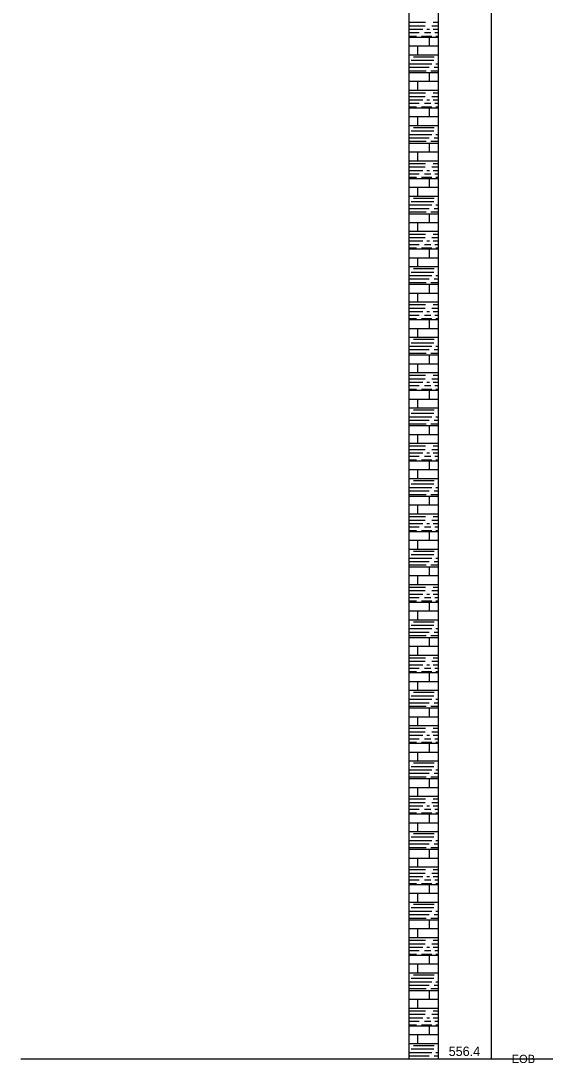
# Model space of a CAD drawing. Extents: x -0.01 to 0.83, y -0.77 to 1.27.
# Drawn here: x 0 to 0.372, y -0.768 to -0.03 of the extents above; entities that cross this region are included whole.
import ezdxf

# ---------------------------------------------------------------- set-up
doc = ezdxf.new("R2010")
doc.units = 0

msp = doc.modelspace()

# ---------------------------------------------------------------- linework, layer by layer
for points in [[(0.29583, 1.22083), (0.29583, -0.76533)], [(0.29583, 1.22083), (0.29583, -0.76533)], [(0.33333, 1.22083), (0.33333, -0.76533)], [(0.33333, 1.22083), (0.33333, -0.76533)], [(0.275, 1.19583), (0.275, -0.76533)], [(0.275, 0.09567), (0.275, -0.76533)], [(0.275, -0.03125), (0.28683, -0.03125)], [(0.275, -0.03375), (0.28642, -0.03375)], [(0.275, -0.03617), (0.28483, -0.03617)], [(0.28767, -0.03617), (0.28967, -0.03617)], [(0.29133, -0.03375), (0.29583, -0.03375)], [(0.29217, -0.03125), (0.29583, -0.03125)], [(0.29217, -0.03617), (0.29583, -0.03617)], [(0.275, -0.03858), (0.28233, -0.03858)], [(0.275, -0.04108), (0.28033, -0.04108)], [(0.275, -0.04183), (0.29583, -0.04183)], [(0.284, -0.04108), (0.29133, -0.04108)], [(0.286, -0.03858), (0.2905, -0.03858)], [(0.28958, -0.04808), (0.28958, -0.04183)], [(0.29342, -0.03858), (0.29583, -0.03858)], [(0.29417, -0.04108), (0.29583, -0.04108)], [(0.275, -0.04808), (0.29583, -0.04808)], [(0.28125, -0.05433), (0.28125, -0.04808)], [(0.275, -0.05433), (0.29583, -0.05433)], [(0.27667, -0.05817), (0.29258, -0.05817)], [(0.27825, -0.05575), (0.293, -0.05575)], [(0.29542, -0.05575), (0.29583, -0.05575)], [(0.275, -0.06067), (0.29133, -0.06067)], [(0.275, -0.06308), (0.28933, -0.06308)], [(0.275, -0.06558), (0.28725, -0.06558)], [(0.2905, -0.06558), (0.29583, -0.06558)], [(0.293, -0.06308), (0.29583, -0.06308)], [(0.29417, -0.06067), (0.29583, -0.06067)], [(0.275, -0.06683), (0.29583, -0.06683)], [(0.275, -0.07308), (0.29583, -0.07308)], [(0.28125, -0.07933), (0.28125, -0.07308)], [(0.28958, -0.07308), (0.28958, -0.06683)], [(0.275, -0.07933), (0.29583, -0.07933)], [(0.275, -0.08125), (0.28683, -0.08125)], [(0.275, -0.08375), (0.28642, -0.08375)], [(0.275, -0.08617), (0.28483, -0.08617)], [(0.28767, -0.08617), (0.28967, -0.08617)], [(0.29133, -0.08375), (0.29583, -0.08375)], [(0.29217, -0.08125), (0.29583, -0.08125)], [(0.29217, -0.08617), (0.29583, -0.08617)], [(0.275, -0.08858), (0.28233, -0.08858)], [(0.275, -0.09108), (0.28033, -0.09108)], [(0.275, -0.09183), (0.29583, -0.09183)], [(0.284, -0.09108), (0.29133, -0.09108)], [(0.286, -0.08858), (0.2905, -0.08858)], [(0.28958, -0.09808), (0.28958, -0.09183)], [(0.29342, -0.08858), (0.29583, -0.08858)], [(0.29417, -0.09108), (0.29583, -0.09108)], [(0.275, -0.09808), (0.29583, -0.09808)], [(0.28125, -0.10433), (0.28125, -0.09808)], [(0.275, -0.10433), (0.29583, -0.10433)], [(0.275, -0.11067), (0.29133, -0.11067)], [(0.27667, -0.10817), (0.29258, -0.10817)], [(0.27825, -0.10575), (0.293, -0.10575)], [(0.29417, -0.11067), (0.29583, -0.11067)], [(0.29542, -0.10575), (0.29583, -0.10575)], [(0.275, -0.11308), (0.28933, -0.11308)], [(0.275, -0.11558), (0.28725, -0.11558)], [(0.275, -0.11683), (0.29583, -0.11683)], [(0.28958, -0.12308), (0.28958, -0.11683)], [(0.2905, -0.11558), (0.29583, -0.11558)], [(0.293, -0.11308), (0.29583, -0.11308)], [(0.275, -0.12308), (0.29583, -0.12308)], [(0.28125, -0.12933), (0.28125, -0.12308)], [(0.275, -0.12933), (0.29583, -0.12933)], [(0.275, -0.13125), (0.28683, -0.13125)], [(0.29217, -0.13125), (0.29583, -0.13125)], [(0.275, -0.13375), (0.28642, -0.13375)], [(0.275, -0.13617), (0.28483, -0.13617)], [(0.275, -0.13858), (0.28233, -0.13858)], [(0.286, -0.13858), (0.2905, -0.13858)], [(0.28767, -0.13617), (0.28967, -0.13617)], [(0.29133, -0.13375), (0.29583, -0.13375)], [(0.29217, -0.13617), (0.29583, -0.13617)], [(0.29342, -0.13858), (0.29583, -0.13858)], [(0.275, -0.14108), (0.28033, -0.14108)], [(0.275, -0.14183), (0.29583, -0.14183)], [(0.284, -0.14108), (0.29133, -0.14108)], [(0.28958, -0.14808), (0.28958, -0.14183)], [(0.29417, -0.14108), (0.29583, -0.14108)], [(0.275, -0.14808), (0.29583, -0.14808)], [(0.275, -0.15433), (0.29583, -0.15433)], [(0.28125, -0.15433), (0.28125, -0.14808)], [(0.275, -0.16067), (0.29133, -0.16067)], [(0.27667, -0.15817), (0.29258, -0.15817)], [(0.27825, -0.15575), (0.293, -0.15575)], [(0.29417, -0.16067), (0.29583, -0.16067)], [(0.29542, -0.15575), (0.29583, -0.15575)], [(0.275, -0.16308), (0.28933, -0.16308)], [(0.275, -0.16558), (0.28725, -0.16558)], [(0.275, -0.16683), (0.29583, -0.16683)], [(0.28958, -0.17308), (0.28958, -0.16683)], [(0.2905, -0.16558), (0.29583, -0.16558)], [(0.293, -0.16308), (0.29583, -0.16308)], [(0.275, -0.17308), (0.29583, -0.17308)], [(0.28125, -0.17933), (0.28125, -0.17308)], [(0.275, -0.17933), (0.29583, -0.17933)], [(0.275, -0.18125), (0.28683, -0.18125)], [(0.275, -0.18375), (0.28642, -0.18375)], [(0.29133, -0.18375), (0.29583, -0.18375)], [(0.29217, -0.18125), (0.29583, -0.18125)], [(0.275, -0.18617), (0.28483, -0.18617)], [(0.275, -0.18858), (0.28233, -0.18858)], [(0.275, -0.19108), (0.28033, -0.19108)], [(0.275, -0.19183), (0.29583, -0.19183)], [(0.284, -0.19108), (0.29133, -0.19108)], [(0.286, -0.18858), (0.2905, -0.18858)], [(0.28767, -0.18617), (0.28967, -0.18617)], [(0.28958, -0.19808), (0.28958, -0.19183)], [(0.29217, -0.18617), (0.29583, -0.18617)], [(0.29342, -0.18858), (0.29583, -0.18858)], [(0.29417, -0.19108), (0.29583, -0.19108)], [(0.275, -0.19808), (0.29583, -0.19808)], [(0.28125, -0.20433), (0.28125, -0.19808)], [(0.275, -0.20433), (0.29583, -0.20433)], [(0.27825, -0.20575), (0.293, -0.20575)], [(0.29542, -0.20575), (0.29583, -0.20575)], [(0.275, -0.21067), (0.29133, -0.21067)], [(0.275, -0.21308), (0.28933, -0.21308)], [(0.27667, -0.20817), (0.29258, -0.20817)], [(0.293, -0.21308), (0.29583, -0.21308)], [(0.29417, -0.21067), (0.29583, -0.21067)], [(0.275, -0.21558), (0.28725, -0.21558)], [(0.275, -0.21683), (0.29583, -0.21683)], [(0.28958, -0.22308), (0.28958, -0.21683)], [(0.2905, -0.21558), (0.29583, -0.21558)], [(0.275, -0.22308), (0.29583, -0.22308)], [(0.28125, -0.22933), (0.28125, -0.22308)], [(0.275, -0.22933), (0.29583, -0.22933)], [(0.275, -0.23125), (0.28683, -0.23125)], [(0.275, -0.23375), (0.28642, -0.23375)], [(0.275, -0.23617), (0.28483, -0.23617)], [(0.28767, -0.23617), (0.28967, -0.23617)], [(0.29133, -0.23375), (0.29583, -0.23375)], [(0.29217, -0.23125), (0.29583, -0.23125)], [(0.29217, -0.23617), (0.29583, -0.23617)], [(0.275, -0.23858), (0.28233, -0.23858)], [(0.275, -0.24108), (0.28033, -0.24108)], [(0.275, -0.24183), (0.29583, -0.24183)], [(0.284, -0.24108), (0.29133, -0.24108)], [(0.286, -0.23858), (0.2905, -0.23858)], [(0.28958, -0.24808), (0.28958, -0.24183)], [(0.29342, -0.23858), (0.29583, -0.23858)], [(0.29417, -0.24108), (0.29583, -0.24108)], [(0.275, -0.24808), (0.29583, -0.24808)], [(0.28125, -0.25433), (0.28125, -0.24808)], [(0.275, -0.25433), (0.29583, -0.25433)], [(0.27667, -0.25817), (0.29258, -0.25817)], [(0.27825, -0.25575), (0.293, -0.25575)], [(0.29542, -0.25575), (0.29583, -0.25575)], [(0.275, -0.26067), (0.29133, -0.26067)], [(0.275, -0.26308), (0.28933, -0.26308)], [(0.275, -0.26558), (0.28725, -0.26558)], [(0.2905, -0.26558), (0.29583, -0.26558)], [(0.293, -0.26308), (0.29583, -0.26308)], [(0.29417, -0.26067), (0.29583, -0.26067)], [(0.275, -0.26683), (0.29583, -0.26683)], [(0.28958, -0.27308), (0.28958, -0.26683)], [(0.275, -0.27308), (0.29583, -0.27308)], [(0.275, -0.27933), (0.29583, -0.27933)], [(0.28125, -0.27933), (0.28125, -0.27308)], [(0.275, -0.28125), (0.28683, -0.28125)], [(0.275, -0.28375), (0.28642, -0.28375)], [(0.275, -0.28617), (0.28483, -0.28617)], [(0.28767, -0.28617), (0.28967, -0.28617)], [(0.29133, -0.28375), (0.29583, -0.28375)], [(0.29217, -0.28125), (0.29583, -0.28125)], [(0.29217, -0.28617), (0.29583, -0.28617)], [(0.275, -0.28858), (0.28233, -0.28858)], [(0.275, -0.29108), (0.28033, -0.29108)], [(0.275, -0.29183), (0.29583, -0.29183)], [(0.284, -0.29108), (0.29133, -0.29108)], [(0.286, -0.28858), (0.2905, -0.28858)], [(0.28958, -0.29808), (0.28958, -0.29183)], [(0.29342, -0.28858), (0.29583, -0.28858)], [(0.29417, -0.29108), (0.29583, -0.29108)], [(0.275, -0.29808), (0.29583, -0.29808)], [(0.28125, -0.30433), (0.28125, -0.29808)], [(0.275, -0.30433), (0.29583, -0.30433)], [(0.27667, -0.30817), (0.29258, -0.30817)], [(0.27825, -0.30575), (0.293, -0.30575)], [(0.29542, -0.30575), (0.29583, -0.30575)], [(0.275, -0.31067), (0.29133, -0.31067)], [(0.275, -0.31308), (0.28933, -0.31308)], [(0.275, -0.31558), (0.28725, -0.31558)], [(0.275, -0.31683), (0.29583, -0.31683)], [(0.28958, -0.32308), (0.28958, -0.31683)], [(0.2905, -0.31558), (0.29583, -0.31558)], [(0.293, -0.31308), (0.29583, -0.31308)], [(0.29417, -0.31067), (0.29583, -0.31067)], [(0.275, -0.32308), (0.29583, -0.32308)], [(0.28125, -0.32933), (0.28125, -0.32308)], [(0.275, -0.32933), (0.29583, -0.32933)], [(0.275, -0.33125), (0.28683, -0.33125)], [(0.29217, -0.33125), (0.29583, -0.33125)], [(0.275, -0.33375), (0.28642, -0.33375)], [(0.275, -0.33617), (0.28483, -0.33617)], [(0.275, -0.33858), (0.28233, -0.33858)], [(0.286, -0.33858), (0.2905, -0.33858)], [(0.28767, -0.33617), (0.28967, -0.33617)], [(0.29133, -0.33375), (0.29583, -0.33375)], [(0.29217, -0.33617), (0.29583, -0.33617)], [(0.29342, -0.33858), (0.29583, -0.33858)], [(0.275, -0.34108), (0.28033, -0.34108)], [(0.275, -0.34183), (0.29583, -0.34183)], [(0.284, -0.34108), (0.29133, -0.34108)], [(0.28958, -0.34808), (0.28958, -0.34183)], [(0.29417, -0.34108), (0.29583, -0.34108)], [(0.275, -0.34808), (0.29583, -0.34808)], [(0.28125, -0.35433), (0.28125, -0.34808)], [(0.275, -0.35433), (0.29583, -0.35433)], [(0.275, -0.36067), (0.29133, -0.36067)], [(0.27667, -0.35817), (0.29258, -0.35817)], [(0.27825, -0.35575), (0.293, -0.35575)], [(0.29417, -0.36067), (0.29583, -0.36067)], [(0.29542, -0.35575), (0.29583, -0.35575)], [(0.275, -0.36308), (0.28933, -0.36308)], [(0.275, -0.36558), (0.28725, -0.36558)], [(0.275, -0.36683), (0.29583, -0.36683)], [(0.28958, -0.37308), (0.28958, -0.36683)], [(0.2905, -0.36558), (0.29583, -0.36558)], [(0.293, -0.36308), (0.29583, -0.36308)], [(0.275, -0.37308), (0.29583, -0.37308)], [(0.28125, -0.37933), (0.28125, -0.37308)], [(0.275, -0.37933), (0.29583, -0.37933)], [(0.275, -0.38125), (0.28683, -0.38125)], [(0.275, -0.38375), (0.28642, -0.38375)], [(0.29133, -0.38375), (0.29583, -0.38375)], [(0.29217, -0.38125), (0.29583, -0.38125)], [(0.275, -0.38617), (0.28483, -0.38617)], [(0.275, -0.38858), (0.28233, -0.38858)], [(0.275, -0.39108), (0.28033, -0.39108)], [(0.284, -0.39108), (0.29133, -0.39108)], [(0.286, -0.38858), (0.2905, -0.38858)], [(0.28767, -0.38617), (0.28967, -0.38617)], [(0.29217, -0.38617), (0.29583, -0.38617)], [(0.29342, -0.38858), (0.29583, -0.38858)], [(0.29417, -0.39108), (0.29583, -0.39108)], [(0.275, -0.39183), (0.29583, -0.39183)], [(0.275, -0.39808), (0.29583, -0.39808)], [(0.28125, -0.40433), (0.28125, -0.39808)], [(0.28958, -0.39808), (0.28958, -0.39183)], [(0.275, -0.40433), (0.29583, -0.40433)], [(0.27825, -0.40575), (0.293, -0.40575)], [(0.29542, -0.40575), (0.29583, -0.40575)], [(0.275, -0.41067), (0.29133, -0.41067)], [(0.275, -0.41308), (0.28933, -0.41308)], [(0.27667, -0.40817), (0.29258, -0.40817)], [(0.293, -0.41308), (0.29583, -0.41308)], [(0.29417, -0.41067), (0.29583, -0.41067)], [(0.275, -0.41558), (0.28725, -0.41558)], [(0.275, -0.41683), (0.29583, -0.41683)], [(0.28958, -0.42308), (0.28958, -0.41683)], [(0.2905, -0.41558), (0.29583, -0.41558)], [(0.275, -0.42308), (0.29583, -0.42308)], [(0.28125, -0.42933), (0.28125, -0.42308)], [(0.275, -0.42933), (0.29583, -0.42933)], [(0.275, -0.43125), (0.28683, -0.43125)], [(0.275, -0.43375), (0.28642, -0.43375)], [(0.29133, -0.43375), (0.29583, -0.43375)], [(0.29217, -0.43125), (0.29583, -0.43125)], [(0.275, -0.43617), (0.28483, -0.43617)], [(0.275, -0.43858), (0.28233, -0.43858)], [(0.275, -0.44108), (0.28033, -0.44108)], [(0.275, -0.44183), (0.29583, -0.44183)], [(0.284, -0.44108), (0.29133, -0.44108)], [(0.286, -0.43858), (0.2905, -0.43858)], [(0.28767, -0.43617), (0.28967, -0.43617)], [(0.28958, -0.44808), (0.28958, -0.44183)], [(0.29217, -0.43617), (0.29583, -0.43617)], [(0.29342, -0.43858), (0.29583, -0.43858)], [(0.29417, -0.44108), (0.29583, -0.44108)], [(0.275, -0.44808), (0.29583, -0.44808)], [(0.28125, -0.45433), (0.28125, -0.44808)], [(0.275, -0.45433), (0.29583, -0.45433)], [(0.27825, -0.45575), (0.293, -0.45575)], [(0.29542, -0.45575), (0.29583, -0.45575)], [(0.275, -0.46067), (0.29133, -0.46067)], [(0.275, -0.46308), (0.28933, -0.46308)], [(0.27667, -0.45817), (0.29258, -0.45817)], [(0.293, -0.46308), (0.29583, -0.46308)], [(0.29417, -0.46067), (0.29583, -0.46067)], [(0.275, -0.46558), (0.28725, -0.46558)], [(0.275, -0.46683), (0.29583, -0.46683)], [(0.28958, -0.47308), (0.28958, -0.46683)], [(0.2905, -0.46558), (0.29583, -0.46558)], [(0.275, -0.47308), (0.29583, -0.47308)], [(0.275, -0.47933), (0.29583, -0.47933)], [(0.28125, -0.47933), (0.28125, -0.47308)], [(0.275, -0.48125), (0.28683, -0.48125)], [(0.275, -0.48375), (0.28642, -0.48375)], [(0.275, -0.48617), (0.28483, -0.48617)], [(0.28767, -0.48617), (0.28967, -0.48617)], [(0.29133, -0.48375), (0.29583, -0.48375)], [(0.29217, -0.48125), (0.29583, -0.48125)], [(0.29217, -0.48617), (0.29583, -0.48617)], [(0.275, -0.48858), (0.28233, -0.48858)], [(0.275, -0.49108), (0.28033, -0.49108)], [(0.275, -0.49183), (0.29583, -0.49183)], [(0.284, -0.49108), (0.29133, -0.49108)], [(0.286, -0.48858), (0.2905, -0.48858)], [(0.28958, -0.49808), (0.28958, -0.49183)], [(0.29342, -0.48858), (0.29583, -0.48858)], [(0.29417, -0.49108), (0.29583, -0.49108)], [(0.275, -0.49808), (0.29583, -0.49808)], [(0.28125, -0.50433), (0.28125, -0.49808)], [(0.275, -0.50433), (0.29583, -0.50433)], [(0.27667, -0.50817), (0.29258, -0.50817)], [(0.27825, -0.50575), (0.293, -0.50575)], [(0.29542, -0.50575), (0.29583, -0.50575)], [(0.275, -0.51067), (0.29133, -0.51067)], [(0.275, -0.51308), (0.28933, -0.51308)], [(0.275, -0.51558), (0.28725, -0.51558)], [(0.2905, -0.51558), (0.29583, -0.51558)], [(0.293, -0.51308), (0.29583, -0.51308)], [(0.29417, -0.51067), (0.29583, -0.51067)], [(0.275, -0.51683), (0.29583, -0.51683)], [(0.275, -0.52308), (0.29583, -0.52308)], [(0.28125, -0.52933), (0.28125, -0.52308)], [(0.28958, -0.52308), (0.28958, -0.51683)], [(0.275, -0.52933), (0.29583, -0.52933)], [(0.275, -0.53125), (0.28683, -0.53125)], [(0.29217, -0.53125), (0.29583, -0.53125)], [(0.275, -0.53375), (0.28642, -0.53375)], [(0.275, -0.53617), (0.28483, -0.53617)], [(0.275, -0.53858), (0.28233, -0.53858)], [(0.286, -0.53858), (0.2905, -0.53858)], [(0.28767, -0.53617), (0.28967, -0.53617)], [(0.29133, -0.53375), (0.29583, -0.53375)], [(0.29217, -0.53617), (0.29583, -0.53617)], [(0.29342, -0.53858), (0.29583, -0.53858)], [(0.275, -0.54108), (0.28033, -0.54108)], [(0.275, -0.54183), (0.29583, -0.54183)], [(0.284, -0.54108), (0.29133, -0.54108)], [(0.28958, -0.54808), (0.28958, -0.54183)], [(0.29417, -0.54108), (0.29583, -0.54108)], [(0.275, -0.54808), (0.29583, -0.54808)], [(0.28125, -0.55433), (0.28125, -0.54808)], [(0.275, -0.55433), (0.29583, -0.55433)], [(0.275, -0.56067), (0.29133, -0.56067)], [(0.27667, -0.55817), (0.29258, -0.55817)], [(0.27825, -0.55575), (0.293, -0.55575)], [(0.29417, -0.56067), (0.29583, -0.56067)], [(0.29542, -0.55575), (0.29583, -0.55575)], [(0.275, -0.56308), (0.28933, -0.56308)], [(0.275, -0.56558), (0.28725, -0.56558)], [(0.275, -0.56683), (0.29583, -0.56683)], [(0.28958, -0.57308), (0.28958, -0.56683)], [(0.2905, -0.56558), (0.29583, -0.56558)], [(0.293, -0.56308), (0.29583, -0.56308)], [(0.275, -0.57308), (0.29583, -0.57308)], [(0.28125, -0.57933), (0.28125, -0.57308)], [(0.275, -0.57933), (0.29583, -0.57933)], [(0.275, -0.58125), (0.28683, -0.58125)], [(0.29217, -0.58125), (0.29583, -0.58125)], [(0.275, -0.58375), (0.28642, -0.58375)], [(0.275, -0.58617), (0.28483, -0.58617)], [(0.275, -0.58858), (0.28233, -0.58858)], [(0.286, -0.58858), (0.2905, -0.58858)], [(0.28767, -0.58617), (0.28967, -0.58617)], [(0.29133, -0.58375), (0.29583, -0.58375)], [(0.29217, -0.58617), (0.29583, -0.58617)], [(0.29342, -0.58858), (0.29583, -0.58858)], [(0.275, -0.59108), (0.28033, -0.59108)], [(0.275, -0.59183), (0.29583, -0.59183)], [(0.284, -0.59108), (0.29133, -0.59108)], [(0.28958, -0.59808), (0.28958, -0.59183)], [(0.29417, -0.59108), (0.29583, -0.59108)], [(0.275, -0.59808), (0.29583, -0.59808)], [(0.275, -0.60433), (0.29583, -0.60433)], [(0.28125, -0.60433), (0.28125, -0.59808)], [(0.275, -0.61067), (0.29133, -0.61067)], [(0.27667, -0.60817), (0.29258, -0.60817)], [(0.27825, -0.60575), (0.293, -0.60575)], [(0.29417, -0.61067), (0.29583, -0.61067)], [(0.29542, -0.60575), (0.29583, -0.60575)], [(0.275, -0.61308), (0.28933, -0.61308)], [(0.275, -0.61558), (0.28725, -0.61558)], [(0.275, -0.61683), (0.29583, -0.61683)], [(0.28958, -0.62308), (0.28958, -0.61683)], [(0.2905, -0.61558), (0.29583, -0.61558)], [(0.293, -0.61308), (0.29583, -0.61308)], [(0.275, -0.62308), (0.29583, -0.62308)], [(0.28125, -0.62933), (0.28125, -0.62308)], [(0.275, -0.62933), (0.29583, -0.62933)], [(0.275, -0.63125), (0.28683, -0.63125)], [(0.275, -0.63375), (0.28642, -0.63375)], [(0.29133, -0.63375), (0.29583, -0.63375)], [(0.29217, -0.63125), (0.29583, -0.63125)], [(0.275, -0.63617), (0.28483, -0.63617)], [(0.275, -0.63858), (0.28233, -0.63858)], [(0.275, -0.64108), (0.28033, -0.64108)], [(0.275, -0.64183), (0.29583, -0.64183)], [(0.284, -0.64108), (0.29133, -0.64108)], [(0.286, -0.63858), (0.2905, -0.63858)], [(0.28767, -0.63617), (0.28967, -0.63617)], [(0.28958, -0.64808), (0.28958, -0.64183)], [(0.29217, -0.63617), (0.29583, -0.63617)], [(0.29342, -0.63858), (0.29583, -0.63858)], [(0.29417, -0.64108), (0.29583, -0.64108)], [(0.275, -0.64808), (0.29583, -0.64808)], [(0.28125, -0.65433), (0.28125, -0.64808)], [(0.275, -0.65433), (0.29583, -0.65433)], [(0.27825, -0.65575), (0.293, -0.65575)], [(0.29542, -0.65575), (0.29583, -0.65575)], [(0.275, -0.66067), (0.29133, -0.66067)], [(0.275, -0.66308), (0.28933, -0.66308)], [(0.27667, -0.65817), (0.29258, -0.65817)], [(0.293, -0.66308), (0.29583, -0.66308)], [(0.29417, -0.66067), (0.29583, -0.66067)], [(0.275, -0.66558), (0.28725, -0.66558)], [(0.275, -0.66683), (0.29583, -0.66683)], [(0.28958, -0.67308), (0.28958, -0.66683)], [(0.2905, -0.66558), (0.29583, -0.66558)], [(0.275, -0.67308), (0.29583, -0.67308)], [(0.28125, -0.67933), (0.28125, -0.67308)], [(0.275, -0.67933), (0.29583, -0.67933)], [(0.275, -0.68125), (0.28683, -0.68125)], [(0.275, -0.68375), (0.28642, -0.68375)], [(0.275, -0.68617), (0.28483, -0.68617)], [(0.28767, -0.68617), (0.28967, -0.68617)], [(0.29133, -0.68375), (0.29583, -0.68375)], [(0.29217, -0.68125), (0.29583, -0.68125)], [(0.29217, -0.68617), (0.29583, -0.68617)], [(0.275, -0.68858), (0.28233, -0.68858)], [(0.275, -0.69108), (0.28033, -0.69108)], [(0.275, -0.69183), (0.29583, -0.69183)], [(0.284, -0.69108), (0.29133, -0.69108)], [(0.286, -0.68858), (0.2905, -0.68858)], [(0.28958, -0.69808), (0.28958, -0.69183)], [(0.29342, -0.68858), (0.29583, -0.68858)], [(0.29417, -0.69108), (0.29583, -0.69108)], [(0.275, -0.69808), (0.29583, -0.69808)], [(0.28125, -0.70433), (0.28125, -0.69808)], [(0.275, -0.70433), (0.29583, -0.70433)], [(0.27667, -0.70817), (0.29258, -0.70817)], [(0.27825, -0.70575), (0.293, -0.70575)], [(0.29542, -0.70575), (0.29583, -0.70575)], [(0.275, -0.71067), (0.29133, -0.71067)], [(0.275, -0.71308), (0.28933, -0.71308)], [(0.275, -0.71558), (0.28725, -0.71558)], [(0.2905, -0.71558), (0.29583, -0.71558)], [(0.293, -0.71308), (0.29583, -0.71308)], [(0.29417, -0.71067), (0.29583, -0.71067)], [(0.275, -0.71683), (0.29583, -0.71683)], [(0.275, -0.72308), (0.29583, -0.72308)], [(0.28125, -0.72933), (0.28125, -0.72308)], [(0.28958, -0.72308), (0.28958, -0.71683)], [(0.275, -0.72933), (0.29583, -0.72933)], [(0.275, -0.73125), (0.28683, -0.73125)], [(0.275, -0.73375), (0.28642, -0.73375)], [(0.275, -0.73617), (0.28483, -0.73617)], [(0.28767, -0.73617), (0.28967, -0.73617)], [(0.29133, -0.73375), (0.29583, -0.73375)], [(0.29217, -0.73125), (0.29583, -0.73125)], [(0.29217, -0.73617), (0.29583, -0.73617)], [(0.275, -0.73858), (0.28233, -0.73858)], [(0.275, -0.74108), (0.28033, -0.74108)], [(0.275, -0.74183), (0.29583, -0.74183)], [(0.284, -0.74108), (0.29133, -0.74108)], [(0.286, -0.73858), (0.2905, -0.73858)], [(0.28958, -0.74808), (0.28958, -0.74183)], [(0.29342, -0.73858), (0.29583, -0.73858)], [(0.29417, -0.74108), (0.29583, -0.74108)], [(0.275, -0.74808), (0.29583, -0.74808)], [(0.28125, -0.75433), (0.28125, -0.74808)], [(0.275, -0.75433), (0.29583, -0.75433)], [(0.27667, -0.75817), (0.29258, -0.75817)], [(0.27825, -0.75575), (0.293, -0.75575)], [(0.29542, -0.75575), (0.29583, -0.75575)], [(0, -0.76533), (0.275, -0.76533)], [(0.275, -0.76067), (0.29133, -0.76067)], [(0.275, -0.76308), (0.28933, -0.76308)], [(0.275, -0.76533), (0.29583, -0.76533)], [(0.275, -0.76533), (0.29583, -0.76533)], [(0.293, -0.76308), (0.29583, -0.76308)], [(0.29417, -0.76067), (0.29583, -0.76067)], [(0.29583, -0.76533), (0.33333, -0.76533)], [(0.33333, -0.76533), (0.37917, -0.76533)]]:
    msp.add_lwpolyline(points)

# ---------------------------------------------------------------- texts
for s, height, p in [('556.4', 0.006667, (0.30316, -0.76329)), ('EOB', 0.005833, (0.34786, -0.76825))]:
    msp.add_text(s, height=height).set_placement(p)

doc.saveas('drawing.dxf')
